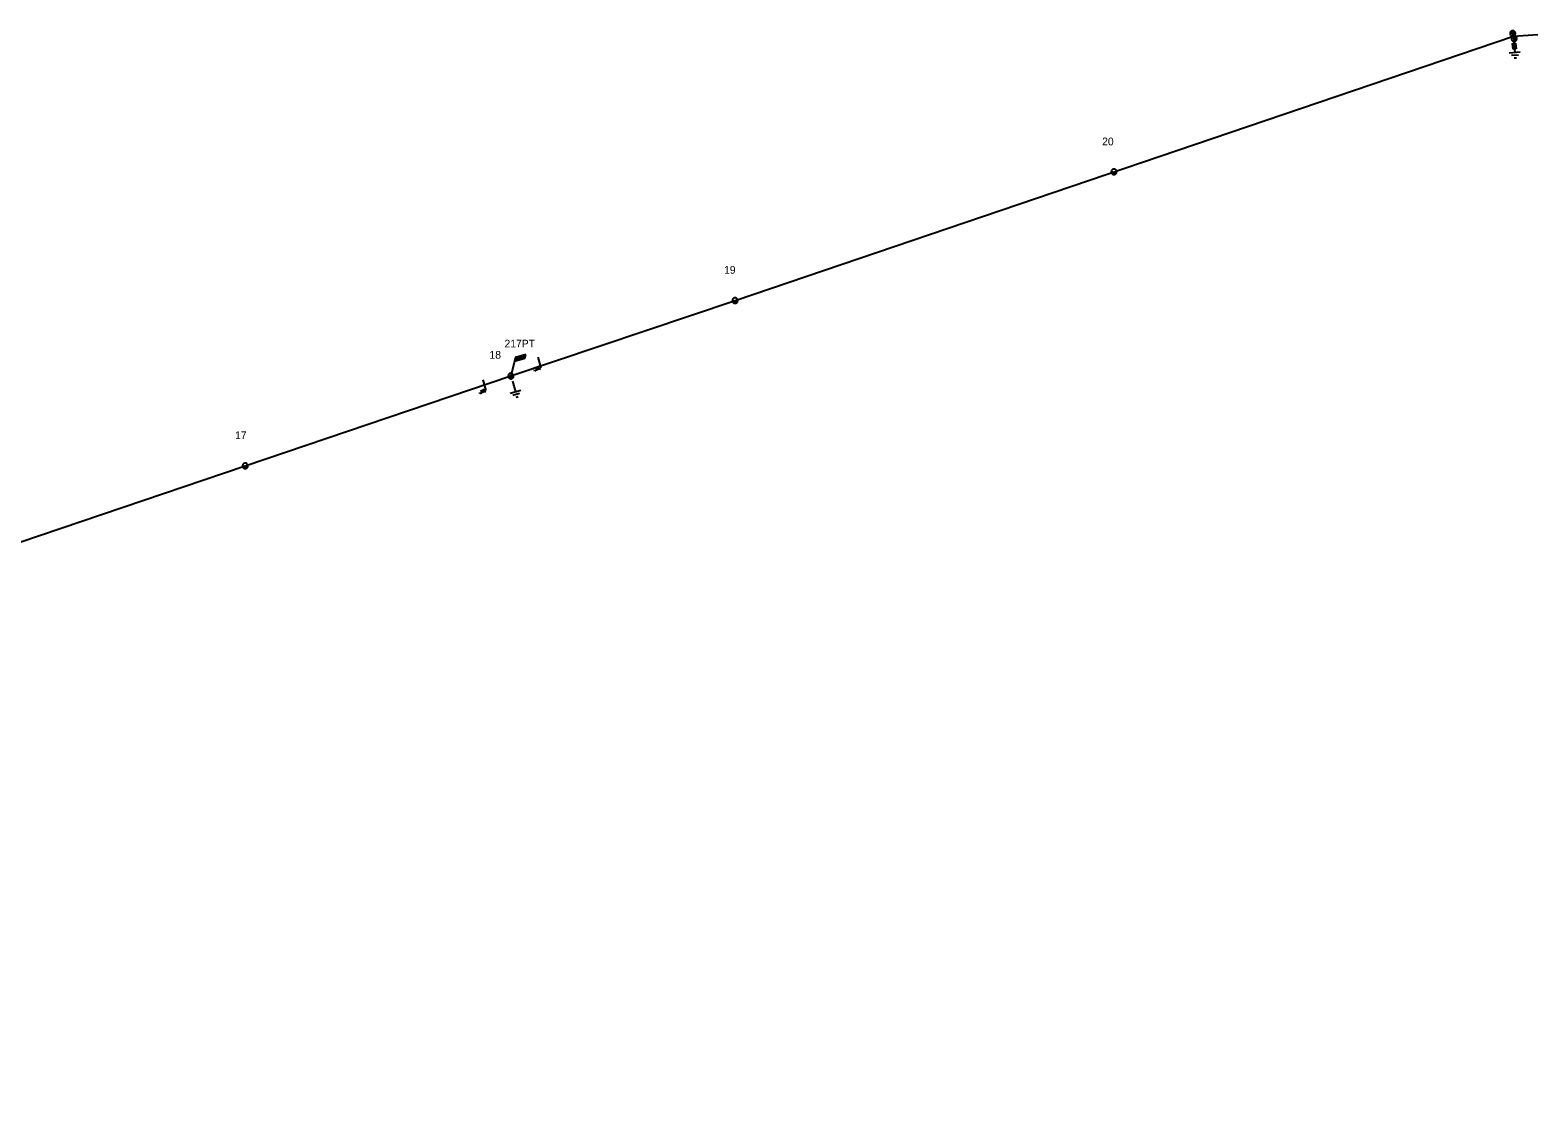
# Model space of a CAD drawing. Extents: x -788491 to -785797, y -1154753 to -1152002.
# Drawn here: x -786137.2 to -785796.6, y -1153308.2 to -1153065.2 of the extents above; entities that cross this region are included whole.
import ezdxf

# ---------------------------------------------------------------- set-up
doc = ezdxf.new("R2010")
doc.units = 0
for name, color, linetype in [('Default', 7, 'Continuous'), ('Vrstva 1', 7, 'Continuous'), ('Vrstva 11', 7, 'Continuous'), ('Vrstva 12', 7, 'Continuous'), ('Vrstva 13', 7, 'Continuous'), ('Vrstva 14', 7, 'Continuous'), ('Vrstva 15', 7, 'Continuous'), ('Vrstva 16', 7, 'Continuous'), ('Vrstva 18', 7, 'Continuous'), ('Vrstva 2', 7, 'Continuous')]:
    doc.layers.add(name, color=color, linetype=linetype)

# ---------------------------------------------------------------- blocks, each defined once
blk = doc.blocks.new('VN840')
at = {"layer": 'Vrstva 15'}
for points in [[(-0.01, 1.41), (-0.01, -1.09)], [(-1.51, -1.24), (-1.51, -1.15)], [(-1.48, -1.35), (-1.51, -1.24)], [(-1.33, -1.42), (-1.48, -1.35)], [(-1.27, -1.42), (-1.33, -1.42)], [(-1.13, -1.35), (-1.27, -1.42)], [(-1.09, -1.24), (-1.13, -1.35)], [(-1.09, -0.59), (-1.09, -1.24)], [(-0.68, -0.59), (-0.68, -1.42)], [(-0.68, -1.11), (-0.27, -0.59)], [(-0.54, -0.94), (-0.2, -1.42)]]:
    blk.add_lwpolyline(points, dxfattribs=at)
blk = doc.blocks.new('VN440')
at = {"layer": 'Vrstva 2'}
for points in [[(1.22, 0), (1.21, 0.13), (1.19, 0.25), (1.16, 0.38), (1.11, 0.5), (1.05, 0.61), (0.98, 0.72), (0.9, 0.82), (0.81, 0.91), (0.71, 0.99), (0.6, 1.06), (0.49, 1.12), (0.37, 1.16), (0.25, 1.2), (0.12, 1.22), (-0.01, 1.22), (-0.14, 1.22), (-0.26, 1.2), (-0.39, 1.16), (-0.51, 1.12), (-0.62, 1.06), (-0.73, 0.99), (-0.83, 0.91), (-0.92, 0.82), (-1, 0.72), (-1.07, 0.61), (-1.13, 0.5), (-1.18, 0.38), (-1.21, 0.25), (-1.23, 0.13), (-1.24, 0), (-1.23, -0.13), (-1.21, -0.26), (-1.18, -0.38), (-1.13, -0.5), (-1.07, -0.62), (-1, -0.73), (-0.92, -0.83), (-0.83, -0.92), (-0.73, -1), (-0.62, -1.07), (-0.51, -1.13), (-0.39, -1.17), (-0.26, -1.2), (-0.14, -1.23), (-0.01, -1.23), (0.12, -1.23), (0.25, -1.2), (0.37, -1.17), (0.49, -1.13), (0.6, -1.07), (0.71, -1), (0.81, -0.92), (0.9, -0.83), (0.98, -0.73), (1.05, -0.62), (1.11, -0.5), (1.16, -0.38), (1.19, -0.26), (1.21, -0.13), (1.22, 0)], [(-1.24, 0), (1.22, 0)], [(-1.18, -0.34), (1.1, -0.34)], [(-1.01, -0.63), (0.97, -0.63)], [(-0.74, -0.92), (0.68, -0.92)]]:
    blk.add_lwpolyline(points, dxfattribs=at)
blk = doc.blocks.new('VN820')
at = {"layer": 'Vrstva 13'}
for points in [[(0, 0), (0, -2.1)], [(-0.32, -1.63), (0.34, -1.63)], [(-0.32, -2.95), (-0.32, -1.63)], [(0.34, -2.95), (-0.32, -2.95)], [(0, -2.1), (-0.12, -1.86)], [(0, -2.1), (0.12, -1.86)], [(0, -2.95), (0, -3.75)], [(0.34, -1.63), (0.34, -2.95)]]:
    blk.add_lwpolyline(points, dxfattribs=at)
blk = doc.blocks.new('VN810')
at = {"layer": 'Vrstva 14'}
for points in [[(0, -1.25), (0, -3.75)], [(1.25, -3.75), (-1.25, -3.75)], [(0.77, -4.37), (-0.8, -4.37)], [(0, -5), (-0.25, -5)], [(0.27, -5), (0, -5)]]:
    blk.add_lwpolyline(points, dxfattribs=at)
blk = doc.blocks.new('VN450')
at = {"layer": 'Vrstva 2'}
for points in [[(0, 0), (-0.01, 0.13), (-0.03, 0.25), (-0.06, 0.38), (-0.11, 0.5), (-0.16, 0.61), (-0.23, 0.72), (-0.31, 0.82), (-0.4, 0.91), (-0.5, 0.99), (-0.61, 1.06), (-0.72, 1.11), (-0.84, 1.16), (-0.97, 1.19), (-1.09, 1.21), (-1.22, 1.22), (-1.35, 1.21), (-1.47, 1.19), (-1.59, 1.16), (-1.71, 1.11), (-1.83, 1.06), (-1.93, 0.99), (-2.03, 0.91), (-2.12, 0.82), (-2.2, 0.72), (-2.27, 0.61), (-2.33, 0.5), (-2.38, 0.38), (-2.41, 0.25), (-2.43, 0.13), (-2.44, 0), (-2.43, -0.13), (-2.41, -0.25), (-2.38, -0.38), (-2.33, -0.5), (-2.27, -0.61), (-2.2, -0.72), (-2.12, -0.82), (-2.03, -0.91), (-1.93, -0.99), (-1.83, -1.06), (-1.71, -1.11), (-1.59, -1.16), (-1.47, -1.19), (-1.35, -1.21), (-1.22, -1.22), (-1.09, -1.21), (-0.97, -1.19), (-0.84, -1.16), (-0.72, -1.11), (-0.61, -1.06), (-0.5, -0.99), (-0.4, -0.91), (-0.31, -0.82), (-0.23, -0.72), (-0.16, -0.61), (-0.11, -0.5), (-0.06, -0.38), (-0.03, -0.25), (-0.01, -0.13), (0, 0)], [(-2.44, 0), (2.44, 0)], [(2.44, 0), (2.43, 0.13), (2.41, 0.25), (2.38, 0.38), (2.33, 0.5), (2.27, 0.61), (2.2, 0.72), (2.12, 0.82), (2.03, 0.91), (1.94, 0.99), (1.83, 1.06), (1.71, 1.11), (1.6, 1.16), (1.47, 1.19), (1.35, 1.21), (1.22, 1.22), (1.09, 1.21), (0.97, 1.19), (0.84, 1.16), (0.72, 1.11), (0.61, 1.06), (0.5, 0.99), (0.4, 0.91), (0.31, 0.82), (0.23, 0.72), (0.16, 0.61), (0.11, 0.5), (0.06, 0.38), (0.03, 0.25), (0.01, 0.13), (0, 0), (0.01, -0.13), (0.03, -0.25), (0.06, -0.38), (0.11, -0.5), (0.16, -0.61), (0.23, -0.72), (0.31, -0.82), (0.4, -0.91), (0.5, -0.99), (0.61, -1.06), (0.72, -1.11), (0.84, -1.16), (0.97, -1.19), (1.09, -1.21), (1.22, -1.22), (1.35, -1.21), (1.47, -1.19), (1.6, -1.16), (1.71, -1.11), (1.83, -1.06), (1.94, -0.99), (2.03, -0.91), (2.12, -0.82), (2.2, -0.72), (2.27, -0.61), (2.33, -0.5), (2.38, -0.38), (2.41, -0.25), (2.43, -0.13), (2.44, 0)], [(-2.4, -0.31), (-0.04, -0.31)], [(-2.26, -0.61), (-0.17, -0.61)], [(-2.01, -0.92), (-0.42, -0.92)], [(0.04, -0.31), (2.4, -0.31)], [(0.17, -0.61), (2.27, -0.61)], [(0.42, -0.92), (2.02, -0.92)]]:
    blk.add_lwpolyline(points, dxfattribs=at)
blk = doc.blocks.new('VN001')
at = {"layer": 'Default'}
for p, q in [((1.96, 3.43), (4.37, 3.43)), ((1.99, 3.48), (4.4, 3.48)), ((2.02, 3.53), (4.43, 3.53)), ((2.05, 3.58), (4.46, 3.58)), ((2.07, 3.63), (4.49, 3.63)), ((2.1, 3.68), (4.52, 3.68)), ((2.13, 3.73), (2.54, 3.73)), ((1.73, 3.03), (4.14, 3.03)), ((1.76, 3.08), (4.17, 3.08)), ((1.79, 3.13), (4.2, 3.13)), ((1.82, 3.18), (4.23, 3.18)), ((1.85, 3.23), (4.26, 3.23)), ((1.87, 3.28), (4.29, 3.28)), ((1.9, 3.33), (4.32, 3.33)), ((1.93, 3.38), (4.35, 3.38))]:
    blk.add_line(p, q, dxfattribs=at)
blk.add_lwpolyline([(2.13, 3.73), (0, 0)], dxfattribs=at)
blk.add_lwpolyline([(4.55, 3.73), (2.13, 3.73), (1.7, 2.98), (4.12, 2.99)], close=True, dxfattribs=at)

msp = doc.modelspace()

# ---------------------------------------------------------------- linework, layer by layer
at = {"layer": 'Vrstva 1'}
for points in [[(-786028.55, -1153143.31), (-785977.91, -1153126.28), (-785802.06, -1153066.54), (-785796.56, -1153066.21)], [(-786516.04, -1153308.16), (-786363.07, -1153256.35), (-786176.45, -1153193.34), (-786028.55, -1153143.31)]]:
    msp.add_lwpolyline(points, dxfattribs=at)

# ---------------------------------------------------------------- block references
at = {"layer": 'Vrstva 11', "rotation": 16.067366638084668}
msp.add_blockref('VN001', (-786028.55, -1153143.31), dxfattribs=at)
at = {"layer": 'Vrstva 13', "xscale": 0.5, "yscale": 0.5}
for name, p, rotation in [('VN450', (-785802.06, -1153066.54), 106.06736665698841), ('VN440', (-785892.31, -1153097.2), 16.067366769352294), ('VN440', (-785977.91, -1153126.28), 16.067366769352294), ('VN440', (-786028.55, -1153143.31), 16.067366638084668), ('VN440', (-786088.56, -1153163.61), 16.067366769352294)]:
    msp.add_blockref(name, p, dxfattribs=dict(at, rotation=rotation))
at = {"layer": 'Vrstva 15'}
for p, rotation in [((-785802.06, -1153066.54), 4.465647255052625), ((-786028.55, -1153143.31), 16.067366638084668)]:
    msp.add_blockref('VN810', p, dxfattribs=dict(at, rotation=rotation))
at = {"layer": 'Vrstva 16', "rotation": 4.457322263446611}
msp.add_blockref('VN820', (-785802.06, -1153066.54), dxfattribs=at)
at = {"layer": 'Vrstva 18', "rotation": 16.067366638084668}
for p in [(-786022.1, -1153140.41), (-786034.49, -1153145.55)]:
    msp.add_blockref('VN840', p, dxfattribs=at)

# ---------------------------------------------------------------- texts
at = {"layer": 'Vrstva 12'}
msp.add_text('217PT', height=1.75, dxfattribs=at).set_placement((-786030, -1153136.87))
at = {"layer": 'Vrstva 14'}
for s, p in [('20', (-785894.99, -1153091.21)), ('19', (-785980.4, -1153120.22)), ('18', (-786033.39, -1153139.41)), ('17', (-786090.87, -1153157.58))]:
    msp.add_text(s, height=1.75, dxfattribs=at).set_placement(p)

doc.saveas('drawing.dxf')
